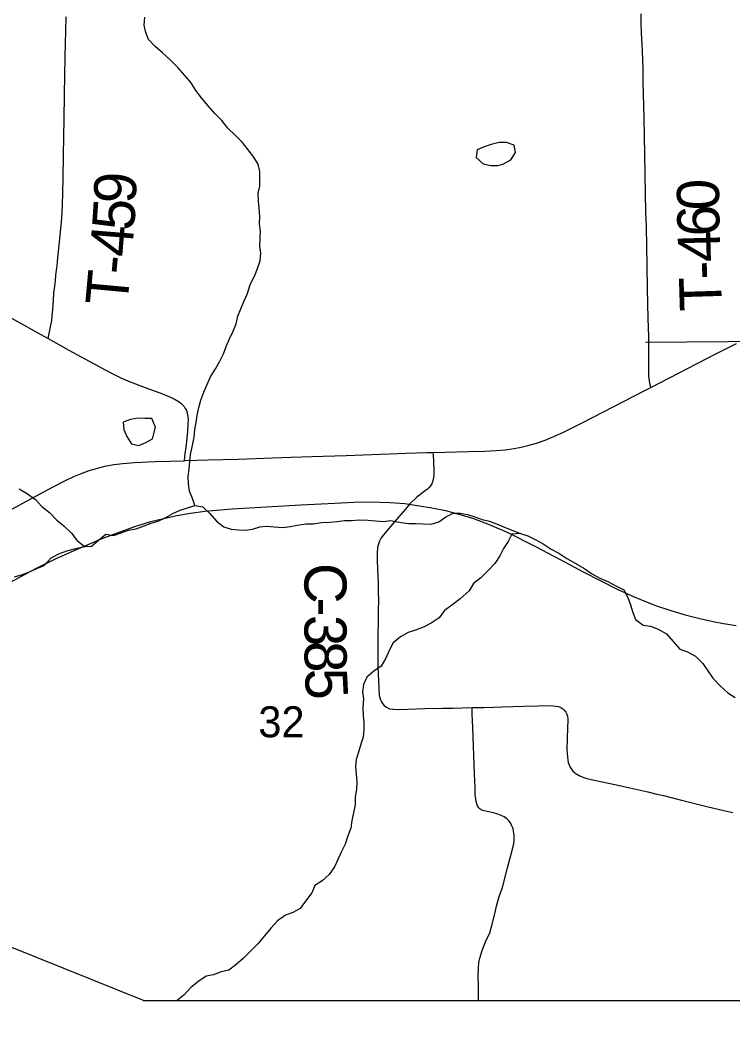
# Model space of a CAD drawing. Extents: x 0 to 34, y 0 to 22.
# Drawn here: x 5.253 to 6.214, y 16.828 to 18.172 of the extents above; entities that cross this region are included whole.
import ezdxf

# ---------------------------------------------------------------- set-up
doc = ezdxf.new("R2010")
doc.units = 0
for name, color, linetype in [('GM_X_County_Road', 7, 'Continuous'), ('GM_X_County_Road_Text', 7, 'Continuous'), ('GM_X_County_Text', 7, 'Continuous'), ('GM_X_Interchange_Ramps', 7, 'Continuous'), ('GM_X_Minor_River_Text', 7, 'Continuous'), ('GM_X_Section_Text', 7, 'Continuous'), ('GM_X_State_Location', 7, 'Continuous'), ('GM_X_State_Route', 7, 'Continuous'), ('GM_X_Township_Road', 7, 'Continuous'), ('GM_X_Township_Text', 7, 'Continuous'), ('SH_Text', 7, 'Continuous')]:
    doc.layers.add(name, color=color, linetype=linetype)

msp = doc.modelspace()

# ---------------------------------------------------------------- linework, layer by layer
at = {"layer": 'GM_X_County_Road'}
msp.add_lwpolyline([(5.2137, 17.4969), (5.2573, 17.5207), (5.2983, 17.5429), (5.3149, 17.5514), (5.3262, 17.5567), (5.3349, 17.5604), (5.3466, 17.5646), (5.3586, 17.5681), (5.3677, 17.5704), (5.3799, 17.5727), (5.3923, 17.5743), (5.4078, 17.5755), (5.4358, 17.5767), (5.4748, 17.5779), (5.4762, 17.578), (5.5073, 17.5789), (5.5476, 17.5801), (5.5941, 17.5819), (5.619, 17.5828), (5.647, 17.5835), (5.6935, 17.5849), (5.7743, 17.5879), (5.8022, 17.5888), (5.8101, 17.589), (5.8582, 17.5903), (5.8799, 17.5909), (5.8954, 17.5917), (5.9077, 17.5927), (5.92, 17.5943), (5.9291, 17.5961), (5.9381, 17.5983), (5.95, 17.6017), (5.9617, 17.6058), (5.9732, 17.6104), (5.9873, 17.6168), (6.0122, 17.6295), (6.0951, 17.6722), (6.1039, 17.6767), (6.1918, 17.7219), (6.2195, 17.7361)], dxfattribs=at)
at = {"layer": 'GM_X_County_Road_Text'}
for points in [[(5.4893, 17.5174), (5.486, 17.5269), (5.4819, 17.5368), (5.4808, 17.5467), (5.4802, 17.5565), (5.4818, 17.5667), (5.4826, 17.577), (5.4834, 17.5864), (5.4862, 17.5986), (5.4882, 17.6095), (5.4894, 17.6198), (5.491, 17.6296), (5.4922, 17.6395), (5.4946, 17.6497), (5.4973, 17.6595), (5.5012, 17.6701), (5.5054, 17.6799), (5.5105, 17.6912), (5.517, 17.7018), (5.5231, 17.712), (5.5278, 17.7222), (5.5316, 17.732), (5.5359, 17.7422), (5.5409, 17.7524), (5.5448, 17.7622), (5.5471, 17.7728), (5.5514, 17.7826), (5.5556, 17.7932), (5.5603, 17.8034), (5.5638, 17.8155), (5.5699, 17.8268), (5.5738, 17.8371), (5.5773, 17.8473), (5.5782, 17.8575), (5.5771, 17.867), (5.5772, 17.8772), (5.578, 17.8874), (5.5766, 17.8973), (5.5767, 17.9068), (5.576, 17.9182), (5.5753, 17.9284), (5.5747, 17.9383), (5.577, 17.9481), (5.5771, 17.9576), (5.5768, 17.9679), (5.5746, 17.9774), (5.569, 17.9869), (5.5611, 17.9968), (5.5536, 18.0067), (5.5435, 18.0167), (5.5337, 18.0263), (5.5258, 18.0366), (5.5164, 18.0461), (5.5067, 18.0568), (5.4984, 18.0668), (5.4905, 18.0767), (5.4842, 18.087), (5.4759, 18.0973), (5.4665, 18.1077), (5.456, 18.118), (5.4455, 18.1276), (5.4357, 18.136), (5.427, 18.1456), (5.4233, 18.1551), (5.4211, 18.1649), (5.422, 18.1756)], [(5.2526, 17.54), (5.2624, 17.5342), (5.2745, 17.5258), (5.2831, 17.5162), (5.2933, 17.5082), (5.303, 17.4978), (5.3128, 17.4902), (5.323, 17.4802), (5.3301, 17.4707), (5.3403, 17.4622), (5.3498, 17.4629), (5.3593, 17.4708), (5.3692, 17.479), (5.3794, 17.477), (5.3901, 17.4807), (5.3996, 17.4841), (5.4102, 17.4862), (5.4209, 17.4903), (5.4304, 17.4936), (5.4399, 17.4966), (5.4501, 17.5014), (5.4597, 17.5066), (5.4695, 17.5111), (5.4794, 17.5144), (5.4893, 17.5174), (5.4999, 17.5158), (5.5097, 17.5066), (5.5183, 17.4966), (5.5285, 17.489), (5.5383, 17.4855), (5.5482, 17.4846), (5.5576, 17.4845), (5.5671, 17.4856), (5.577, 17.4889), (5.5865, 17.4896), (5.5963, 17.4887), (5.6081, 17.4879), (5.6176, 17.4893), (5.6274, 17.4911), (5.6388, 17.4929), (5.6494, 17.4928), (5.6601, 17.4946), (5.6714, 17.4952), (5.6809, 17.4959), (5.6912, 17.4973), (5.7006, 17.4973), (5.7109, 17.4983), (5.7223, 17.4978), (5.7329, 17.497), (5.7438, 17.4961), (5.7533, 17.4972), (5.7673, 17.4948), (5.7776, 17.4935), (5.7874, 17.4931), (5.7969, 17.493), (5.8079, 17.4925), (5.8181, 17.4954), (5.8277, 17.5022), (5.8376, 17.5074), (5.847, 17.5073), (5.8569, 17.5053), (5.8667, 17.5022), (5.8765, 17.4987), (5.8867, 17.4963), (5.8981, 17.492), (5.9079, 17.4878), (5.9283, 17.48), (5.9381, 17.4765), (5.9491, 17.4711), (5.9589, 17.4657), (5.9698, 17.4588), (5.98, 17.4534), (5.9909, 17.4461), (6.0019, 17.4399), (6.0136, 17.433), (6.0241, 17.4261), (6.0351, 17.4195), (6.0468, 17.4149), (6.057, 17.4095), (6.0675, 17.4037), (6.0731, 17.3934), (6.0768, 17.3839), (6.0798, 17.3732), (6.0835, 17.3637), (6.0937, 17.3564)], [(5.9283, 17.48), (5.9165, 17.479), (5.9119, 17.4692), (5.9054, 17.4594), (5.9004, 17.4496), (5.8938, 17.4394), (5.8843, 17.4296), (5.8747, 17.4202), (5.8648, 17.4123), (5.8591, 17.4025), (5.8472, 17.3916), (5.8373, 17.3841), (5.8259, 17.3759), (5.8186, 17.3661), (5.8079, 17.359), (5.7984, 17.3542), (5.787, 17.3497), (5.7771, 17.3464), (5.7664, 17.3404), (5.7565, 17.3325), (5.7515, 17.322), (5.7469, 17.3118), (5.7403, 17.3012), (5.7308, 17.2941), (5.7213, 17.2862), (5.7166, 17.2764), (5.7154, 17.2666), (5.7165, 17.2571), (5.7156, 17.2449), (5.7163, 17.2347), (5.7173, 17.2252), (5.7173, 17.2153), (5.7164, 17.2055), (5.7129, 17.1957), (5.7098, 17.1851), (5.7067, 17.1752), (5.7059, 17.1658), (5.7069, 17.1555), (5.7076, 17.1453), (5.7071, 17.135), (5.7055, 17.1248), (5.7054, 17.1142), (5.7034, 17.1032), (5.7011, 17.093), (5.6995, 17.0828), (5.6956, 17.0722), (5.6921, 17.0612), (5.6871, 17.0514), (5.6825, 17.0412), (5.6774, 17.0306), (5.6705, 17.0201), (5.661, 17.0115), (5.6511, 17.0055), (5.6468, 16.9957), (5.6384, 16.9844), (5.6311, 16.9742), (5.6212, 16.969), (5.6113, 16.9656), (5.6007, 16.9578), (5.5919, 16.948), (5.5831, 16.9378), (5.5743, 16.9269), (5.5647, 16.9175), (5.5548, 16.9074), (5.5445, 16.8987), (5.5349, 16.8912), (5.5247, 16.8891), (5.5144, 16.885), (5.5045, 16.8832), (5.4946, 16.8764), (5.4839, 16.8678), (5.4744, 16.8577), (5.4656, 16.8504)], [(5.2463, 17.4214), (5.2569, 17.4247), (5.2665, 17.428), (5.2763, 17.4328), (5.2859, 17.4366), (5.2954, 17.4471), (5.3068, 17.453), (5.3167, 17.4564), (5.327, 17.4593), (5.3365, 17.4615), (5.3441, 17.4626)], [(6.0937, 17.3564), (6.1035, 17.3548), (6.1141, 17.3509), (6.125, 17.3444), (6.134, 17.3344), (6.1434, 17.3241), (6.1536, 17.3202), (6.1642, 17.3144), (6.1744, 17.3045), (6.1811, 17.2949), (6.1878, 17.285), (6.198, 17.2739), (6.2078, 17.2651), (6.2176, 17.2586)]]:
    msp.add_lwpolyline(points, dxfattribs=at)
at = {"layer": 'GM_X_County_Text'}
msp.add_lwpolyline([(5.236, 17.4114), (5.2564, 17.4226), (5.2759, 17.433), (5.3024, 17.446), (5.3295, 17.4583), (5.3641, 17.473), (5.3849, 17.4809), (5.4084, 17.4891), (5.4299, 17.4958), (5.4472, 17.5002), (5.4649, 17.5042), (5.4833, 17.5074), (5.5026, 17.5099), (5.5394, 17.5129), (5.6321, 17.5183), (5.6778, 17.5208), (5.7035, 17.522), (5.7256, 17.5223), (5.7523, 17.5215), (5.7723, 17.5201), (5.7924, 17.5173), (5.809, 17.5146), (5.8274, 17.5107), (5.8483, 17.5052), (5.8648, 17.5), (5.886, 17.4921), (5.9104, 17.4816), (5.9488, 17.4625), (5.9885, 17.4413), (6.0121, 17.4287), (6.0365, 17.4159), (6.0589, 17.4046), (6.0814, 17.3943), (6.0991, 17.3872), (6.1119, 17.3823), (6.1309, 17.3759), (6.1503, 17.3702), (6.1701, 17.3652), (6.1882, 17.3612), (6.202, 17.3585), (6.2191, 17.356)], dxfattribs=at)
at = {"layer": 'GM_X_Interchange_Ramps'}
for points in [[(5.2916, 17.7428), (5.2952, 17.7606), (5.2963, 17.7671), (5.2971, 17.7727), (5.2975, 17.7777), (5.2976, 17.7813), (5.2986, 17.7941), (5.2993, 17.8039), (5.3, 17.8101), (5.3012, 17.8204), (5.302, 17.8276), (5.3029, 17.8354), (5.3035, 17.8407), (5.3042, 17.8469), (5.3063, 17.8685), (5.3095, 17.8994), (5.3103, 17.9119), (5.3112, 17.9367), (5.3123, 17.9865), (5.3128, 18.0175), (5.3132, 18.0362), (5.3137, 18.0734), (5.314, 18.0952), (5.3145, 18.1231), (5.3153, 18.1573), (5.3156, 18.176)], [(6.1039, 17.6767), (6.1027, 17.6826), (6.1021, 17.6857), (6.1015, 17.6919), (6.1012, 17.6976), (6.1013, 17.7043), (6.1012, 17.7447), (6.1007, 17.7696), (6.0997, 17.8101), (6.0993, 17.8412), (6.0988, 17.866), (6.0981, 17.894), (6.0975, 17.9127), (6.0969, 17.9376), (6.0961, 17.9905), (6.0952, 18.0402), (6.0944, 18.0713), (6.0939, 18.09), (6.0936, 18.1055), (6.0934, 18.1179), (6.093, 18.1303), (6.0915, 18.1552), (6.0911, 18.1676), (6.091, 18.18)], [(4.7242, 17.8736), (4.7513, 17.8735), (4.7823, 17.8729), (4.8196, 17.8727), (4.8786, 17.872), (4.9562, 17.8712), (4.9935, 17.8711), (5.0277, 17.8715), (5.0432, 17.8713), (5.0525, 17.8708), (5.0586, 17.87), (5.0647, 17.8687), (5.0707, 17.867), (5.0764, 17.8647), (5.082, 17.862), (5.0902, 17.8576), (5.1225, 17.8389), (5.1544, 17.8202), (5.1895, 17.8002), (5.2461, 17.7678), (5.2814, 17.7482), (5.2916, 17.7428)], [(5.2916, 17.7428), (5.3057, 17.7344), (5.3193, 17.7269), (5.3467, 17.7123), (5.3684, 17.7004), (5.3794, 17.6946), (5.3906, 17.6892), (5.4021, 17.6844), (5.4224, 17.6767), (5.4457, 17.668), (5.4572, 17.6633), (5.4628, 17.6605), (5.4681, 17.6573), (5.4705, 17.6554), (5.4727, 17.6532), (5.4747, 17.6508), (5.4764, 17.6483), (5.4778, 17.6455), (5.4788, 17.6426), (5.4795, 17.6395), (5.4799, 17.6365), (5.4801, 17.6334), (5.48, 17.6271), (5.4793, 17.6178), (5.4774, 17.5993), (5.4755, 17.5839), (5.4748, 17.5779)], [(5.8717, 16.8504), (5.8717, 16.8566), (5.8716, 16.8708), (5.8715, 16.8825), (5.8717, 16.8938), (5.8723, 16.9015), (5.8736, 16.9077), (5.8768, 16.9176), (5.8813, 16.9294), (5.8868, 16.9415), (5.8903, 16.9532), (5.8936, 16.9673), (5.8958, 16.9776), (5.8996, 16.9907), (5.9039, 17.0029), (5.911, 17.0291), (5.9159, 17.0476), (5.9188, 17.06), (5.9196, 17.0646), (5.9198, 17.0686), (5.9196, 17.0735), (5.9191, 17.078), (5.9187, 17.0805), (5.9182, 17.0823), (5.9179, 17.0834), (5.9173, 17.0847), (5.9164, 17.0869), (5.9148, 17.0897), (5.9129, 17.0922), (5.91, 17.0953), (5.9064, 17.0981), (5.9025, 17.0999), (5.8978, 17.1014), (5.8918, 17.1034), (5.8836, 17.105), (5.8794, 17.106), (5.8776, 17.1066), (5.8754, 17.1075), (5.8741, 17.1082), (5.8731, 17.1091), (5.872, 17.1102), (5.8705, 17.1128), (5.8694, 17.1157), (5.8686, 17.1188), (5.868, 17.1218), (5.8676, 17.1249), (5.8673, 17.128), (5.8671, 17.1373), (5.8665, 17.1559), (5.8651, 17.1931), (5.8641, 17.2177), (5.8637, 17.2279), (5.8634, 17.236), (5.8631, 17.2419), (5.863, 17.2451)]]:
    msp.add_lwpolyline(points, dxfattribs=at)
at = {"layer": 'GM_X_Minor_River_Text'}
for points in [[(5.889, 18.0041), (5.8795, 18.0008), (5.87, 17.9967), (5.8684, 17.9864), (5.8782, 17.978), (5.8884, 17.9756), (5.8979, 17.9759), (5.9044, 17.9778)], [(5.9044, 17.9778), (5.9154, 17.9834), (5.9216, 17.9935), (5.9197, 18.0034), (5.9095, 18.0066), (5.8997, 18.007), (5.889, 18.0041)], [(5.4122, 17.6353), (5.4027, 17.6334), (5.3928, 17.6297), (5.3935, 17.6199), (5.3976, 17.6104), (5.404, 17.6008), (5.4138, 17.5985), (5.4233, 17.6025), (5.4321, 17.6074)], [(5.4321, 17.6074), (5.4364, 17.6233), (5.4311, 17.6347), (5.4217, 17.6348), (5.4122, 17.6353)]]:
    msp.add_lwpolyline(points, dxfattribs=at)
at = {"layer": 'GM_X_State_Route'}
msp.add_lwpolyline([(6.0967, 17.7375), (7.0999, 17.7456), (7.1161, 16.8504)], dxfattribs=at)
at = {"layer": 'GM_X_Township_Road'}
for points in [[(5.8101, 17.589), (5.8104, 17.5852), (5.8109, 17.5769), (5.8113, 17.5649), (5.8114, 17.5585), (5.8112, 17.5555), (5.8108, 17.5524), (5.8099, 17.5495), (5.8086, 17.5467), (5.8069, 17.5441), (5.805, 17.5417), (5.8028, 17.5395), (5.7978, 17.5362), (5.7885, 17.5288), (5.7793, 17.5198), (5.7732, 17.5127), (5.7639, 17.5019), (5.7529, 17.4893), (5.7436, 17.4782), (5.7404, 17.4741), (5.7377, 17.4688), (5.7356, 17.461), (5.7349, 17.4531), (5.7349, 17.4442), (5.7354, 17.4315), (5.7359, 17.4224), (5.7363, 17.4135), (5.7364, 17.4077), (5.7366, 17.4012), (5.7367, 17.3902), (5.7365, 17.3759), (5.7363, 17.3613), (5.7361, 17.3433), (5.736, 17.3259), (5.7361, 17.3006), (5.7372, 17.2713), (5.7379, 17.2613), (5.7395, 17.2555), (5.7408, 17.2529), (5.7424, 17.2507), (5.7441, 17.2486), (5.7466, 17.2464), (5.7518, 17.2437), (5.757, 17.243), (5.7653, 17.2426), (5.7994, 17.2439), (5.8231, 17.2444), (5.8372, 17.2446), (5.863, 17.2451)], [(5.863, 17.2451), (5.8787, 17.2455), (5.8919, 17.2459), (5.9042, 17.2462), (5.9322, 17.247), (5.9527, 17.2475), (5.964, 17.2479), (5.9726, 17.2475), (5.9764, 17.2472), (5.9797, 17.2465), (5.9829, 17.2453), (5.9855, 17.2435), (5.9874, 17.2417), (5.9894, 17.239), (5.9907, 17.2364), (5.9917, 17.2335), (5.992, 17.2301), (5.9922, 17.2266), (5.9919, 17.2189), (5.9911, 17.2025), (5.991, 17.189), (5.9917, 17.1784), (5.9926, 17.171), (5.9951, 17.1647), (5.999, 17.1597), (6.0029, 17.1565), (6.0074, 17.1535), (6.0123, 17.1513), (6.0179, 17.1497), (6.0279, 17.1474), (6.0576, 17.1411), (6.0758, 17.137), (6.1, 17.1315), (6.1121, 17.1287), (6.1212, 17.1265), (6.1453, 17.1205), (6.1815, 17.1115), (6.2026, 17.1065), (6.2148, 17.104)]]:
    msp.add_lwpolyline(points, dxfattribs=at)
at = {"layer": 'SH_Text'}
msp.add_line((5.4199, 16.8504), (7.5483, 16.8504), dxfattribs=at)
msp.add_lwpolyline([(5.4199, 16.8504), (4.7398, 17.1239), (5.4199, 16.5526)], dxfattribs=at)

# ---------------------------------------------------------------- texts
at = {"layer": 'GM_X_Section_Text'}
for s, rotation, p in [('C', 270, (5.637, 17.4401)), ('-', 270.0226, (5.637, 17.3934)), ('3', 270.1079, (5.637, 17.37)), ('8', 270.4142, (5.6371, 17.3346)), ('5', 272.9622, (5.6374, 17.2969))]:
    msp.add_text(s, height=0.0568, rotation=rotation, dxfattribs=at).set_placement(p)
at = {"layer": 'GM_X_State_Location'}
msp.add_text('32', height=0.04186, rotation=0, dxfattribs=at).set_placement((5.5749, 17.2051))
at = {"layer": 'GM_X_Township_Text'}
for s, rotation, p in [('9', 87.7914, (5.4095, 17.9238)), ('0', 90.4527, (6.1963, 17.9158)), ('5', 86.1174, (5.4071, 17.8871)), ('6', 91.374, (6.1971, 17.8811)), ('4', 85.2836, (5.4041, 17.8513)), ('4', 91.6394, (6.1981, 17.8462)), ('-', 84.86, (5.402, 17.8276)), ('T', 84.7427, (5.3981, 17.7852)), ('-', 91.7409, (6.1988, 17.8229)), ('T', 91.7617, (6.2001, 17.7804))]:
    msp.add_text(s, height=0.0568, rotation=rotation, dxfattribs=at).set_placement(p)

doc.saveas('drawing.dxf')
